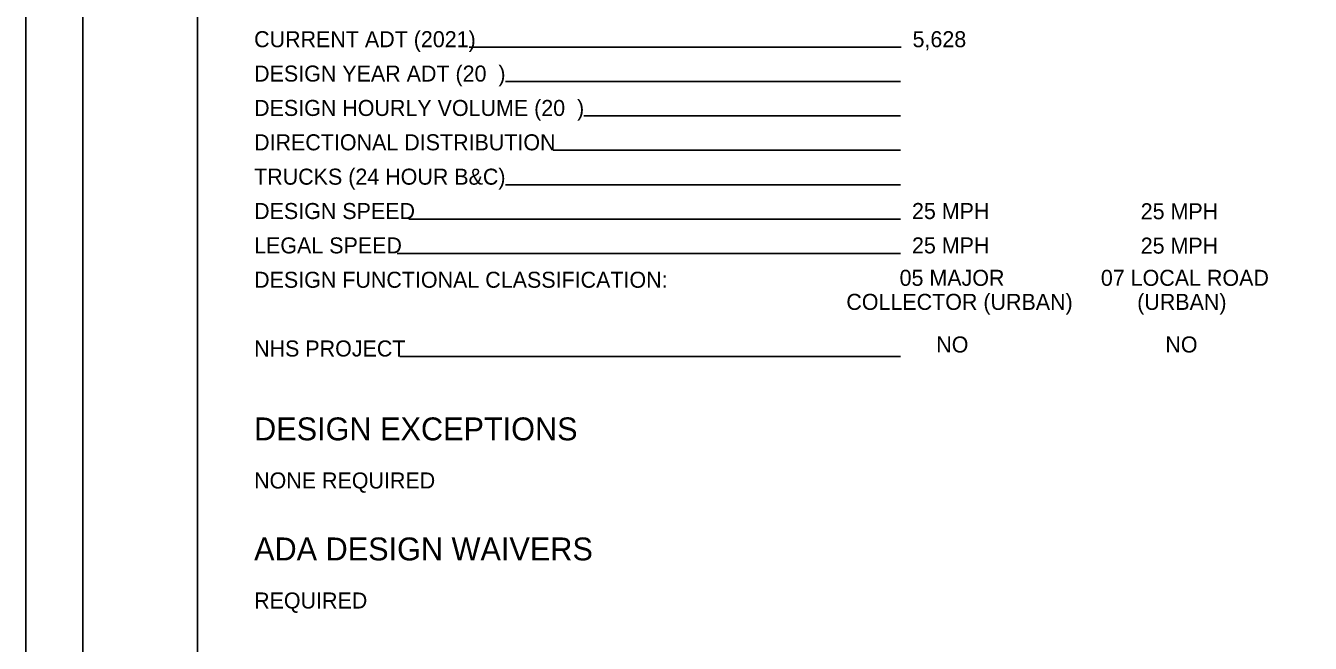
# Model space of a CAD drawing. Extents: x 0 to 45.4, y -2.2 to 22.
# Drawn here: x 0 to 11.21, y 4.6 to 9.99 of the extents above; entities that cross this region are included whole.
import ezdxf

# ---------------------------------------------------------------- set-up
doc = ezdxf.new("R2010")
doc.units = 0
for name, color, linetype in [('SH_Border', 7, 'Continuous'), ('SH_Cut_Line', 7, 'Continuous'), ('SH_Data', 7, 'Continuous'), ('SH_Text', 7, 'Continuous')]:
    doc.layers.add(name, color=color, linetype=linetype)

msp = doc.modelspace()

# ---------------------------------------------------------------- linework, layer by layer
at = {"layer": 'SH_Border'}
for points in [[(0.5, 21.5), (1.5, 21.5), (1.5, 0.5), (0.5, 0.5)], [(1.5, 21.5), (33.5, 21.5), (33.5, 0.5), (1.5, 0.5)]]:
    msp.add_lwpolyline(points, close=True, dxfattribs=at)
at = {"layer": 'SH_Cut_Line'}
msp.add_lwpolyline([(0, 0), (34, 0), (34, 22), (0, 22)], close=True, dxfattribs=at)
at = {"layer": 'SH_Data'}
for p, q in [((7.642, 9.806), (3.871, 9.806)), ((7.637, 9.506), (4.189, 9.506)), ((7.637, 9.206), (4.872, 9.206)), ((7.637, 8.906), (4.604, 8.906)), ((7.637, 8.606), (4.189, 8.606)), ((7.637, 8.306), (3.346, 8.306)), ((7.637, 8.006), (3.242, 8.006)), ((7.637, 7.106), (3.267, 7.106))]:
    msp.add_line(p, q, dxfattribs=at)

# ---------------------------------------------------------------- texts
at = {"layer": 'SH_Text'}
for s, height, p in [('CURRENT ADT (2021)', 0.14, (1.994, 9.806)), ('5,628', 0.14, (7.742, 9.806)), ('DESIGN YEAR ADT (20  )', 0.14, (1.994, 9.506)), ('DESIGN HOURLY VOLUME (20  )', 0.14, (1.994, 9.206)), ('DIRECTIONAL DISTRIBUTION', 0.14, (1.994, 8.906)), ('TRUCKS (24 HOUR B&C)', 0.14, (1.994, 8.606)), ('DESIGN SPEED', 0.14, (1.994, 8.306)), ('25 MPH', 0.14, (7.737, 8.306)), ('25 MPH', 0.14, (9.734, 8.304)), ('LEGAL SPEED', 0.14, (1.994, 8.006)), ('25 MPH', 0.14, (7.737, 8.006)), ('25 MPH', 0.14, (9.734, 8.004)), ('05 MAJOR', 0.14, (7.629, 7.723)), ('07 LOCAL ROAD', 0.14, (9.386, 7.723)), ('DESIGN FUNCTIONAL CLASSIFICATION:', 0.14, (1.994, 7.706)), ('COLLECTOR (URBAN)', 0.14, (7.164, 7.513)), ('(URBAN)', 0.14, (9.703, 7.513)), ('NHS PROJECT', 0.14, (1.994, 7.106)), ('NO', 0.14, (7.949, 7.141)), ('NO', 0.14, (9.949, 7.141)), ('DESIGN EXCEPTIONS', 0.2, (1.994, 6.374)), ('NONE REQUIRED', 0.14, (1.994, 5.954)), ('ADA DESIGN WAIVERS', 0.2, (1.994, 5.326)), ('REQUIRED', 0.14, (1.994, 4.906))]:
    msp.add_text(s, height=height, dxfattribs=at).set_placement(p)

doc.saveas('drawing.dxf')
